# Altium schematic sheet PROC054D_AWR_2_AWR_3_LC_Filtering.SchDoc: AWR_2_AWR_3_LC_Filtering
size 558 x 431 mm; Date: Not shown in title block; ApprovedBy: Not shown in title block; CheckedBy: Not shown in title block; Author: Not shown in title block; CompanyName: Not shown in title block; DrawnBy: a0271760; Engineer: Not shown in title block; Organization: Not shown in title block; Address1: Not shown in title block; Address2: Not shown in title block; Address3: Not shown in title block; Address4: Not shown in title block; DocumentNumber: 7; Revision: Use project pAWRameter SCH_Rev; SheetNumber: 7; SheetTotal: 19; PageSetup: Record=PageOptions¦CenterHorizontal=True¦CenterVertical=True¦PrintScale=1.00¦XCorrection=1.00¦YCorrection=1.00¦PrintKind=0¦BorderSize=5000000¦LeftOffset=0¦BottomOffset=0¦Orientation=2¦PaperLength=1000¦PaperWidth=1000¦Scale=100¦PaperSource=15¦PrintQuality=600¦MediaType=1¦DitherType=10¦PaperKind=Letter¦PrintScaleMode=1
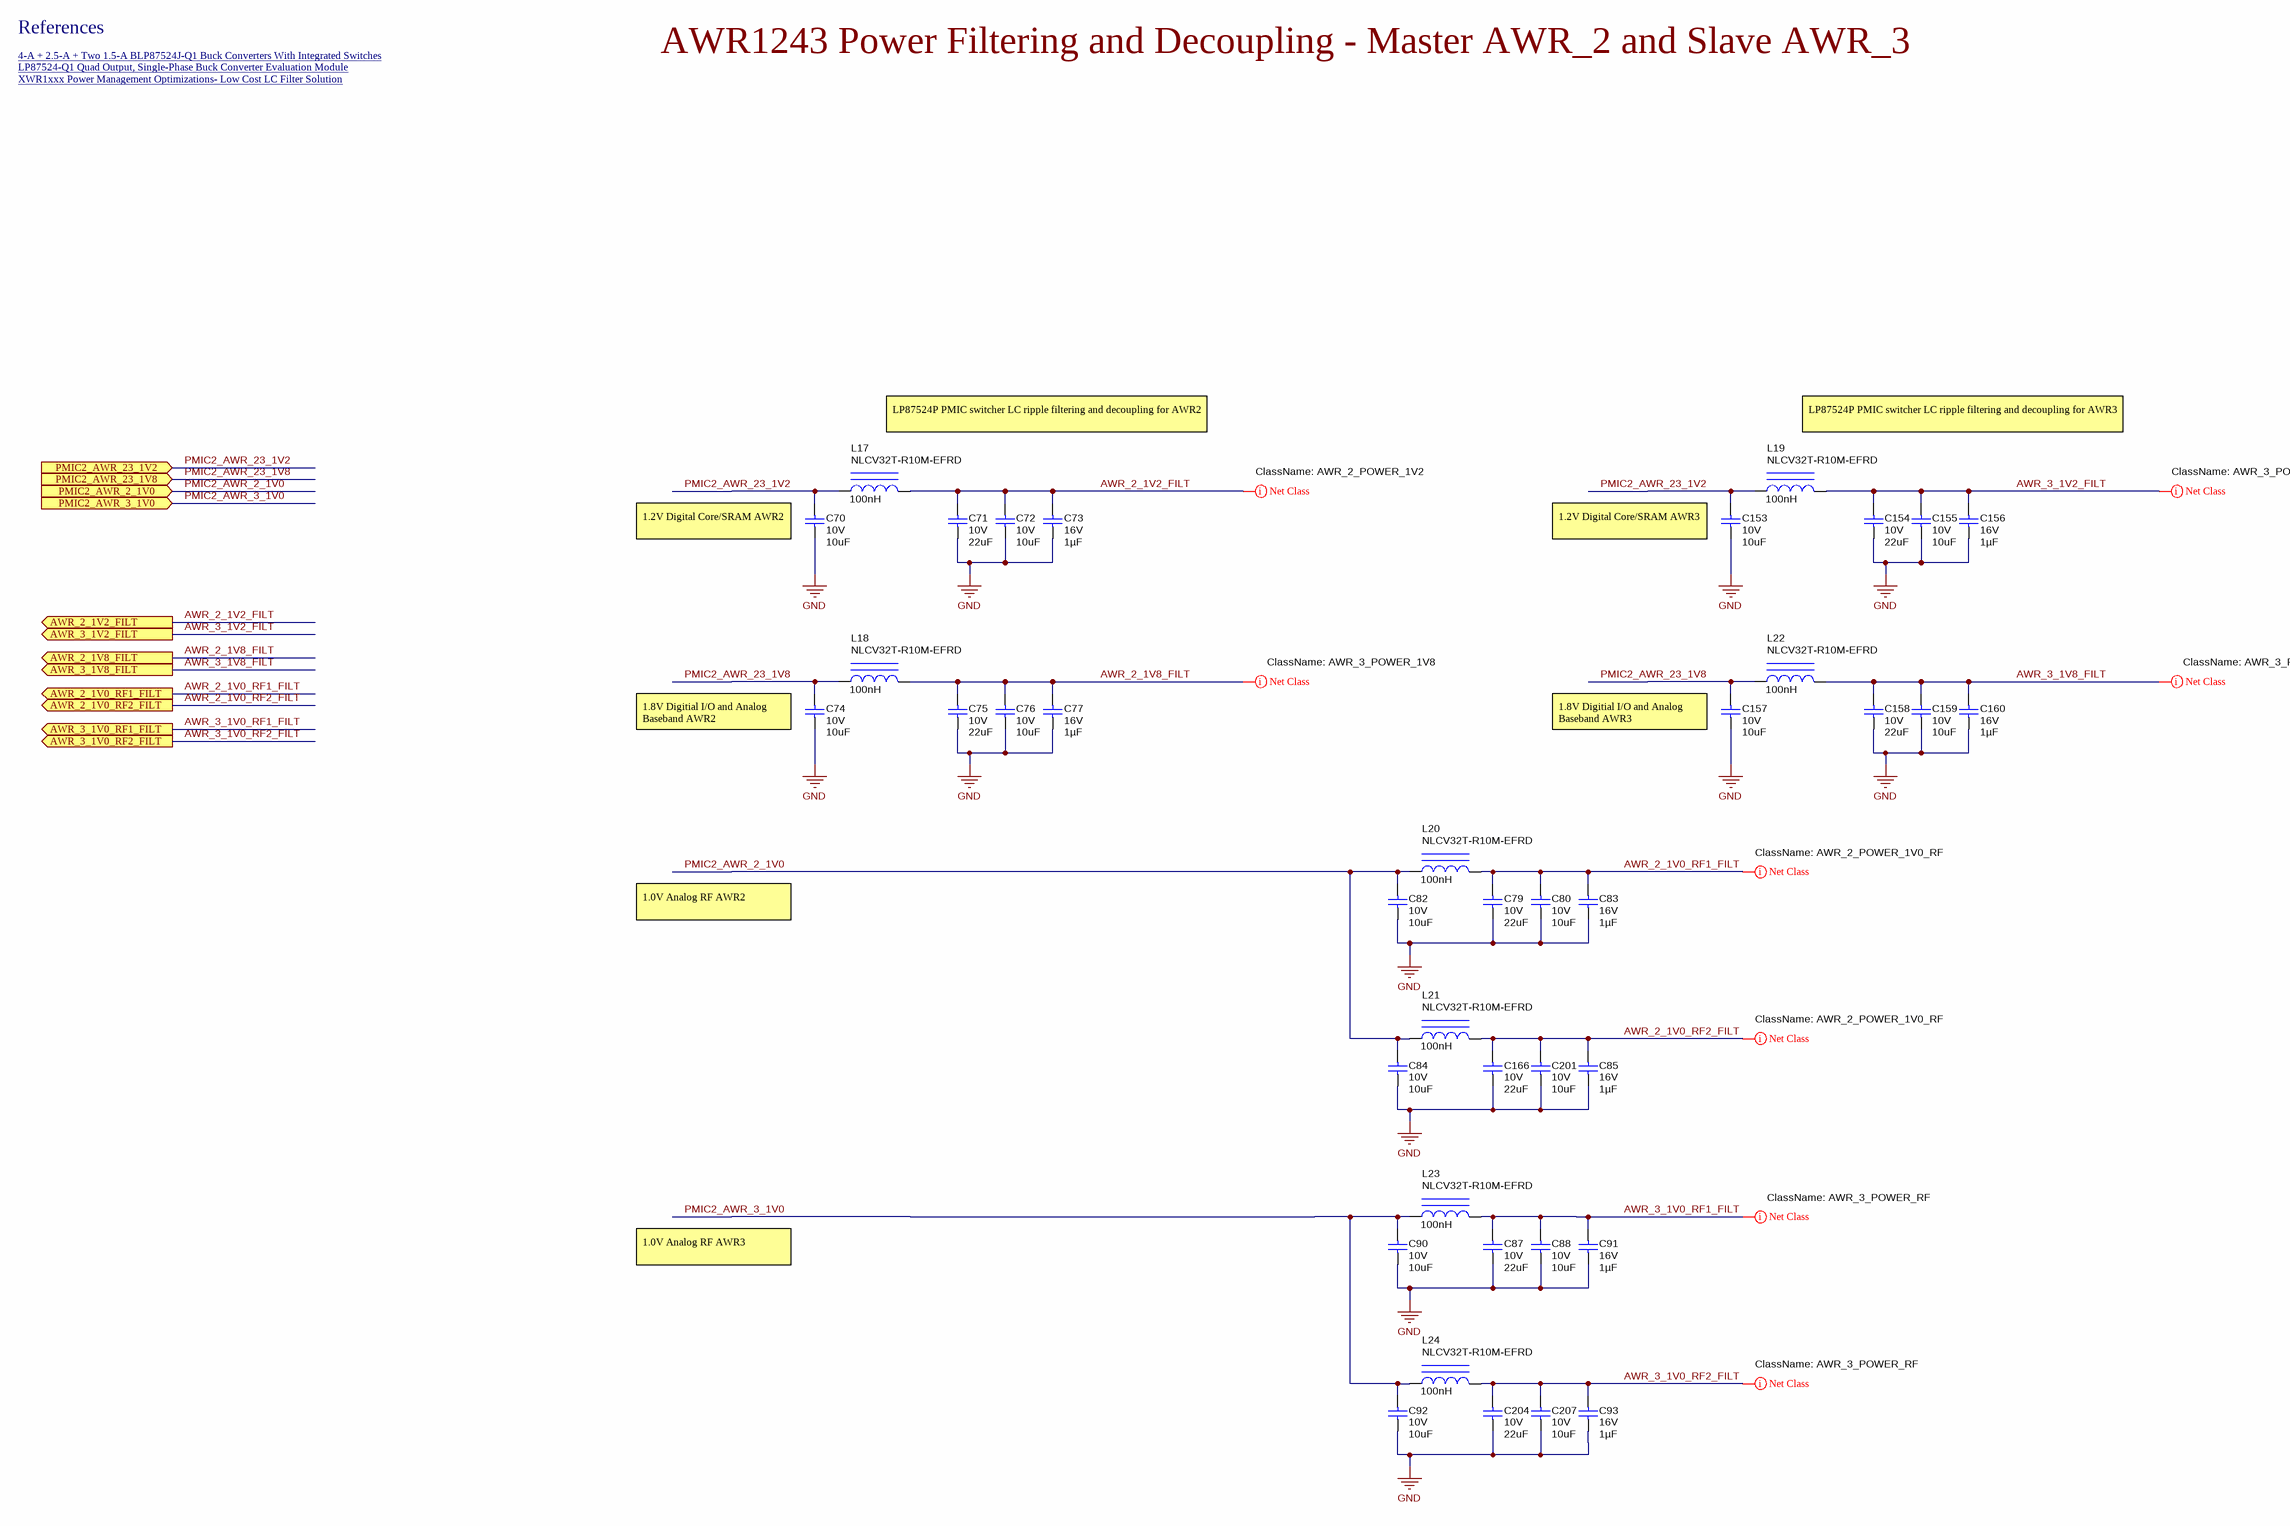
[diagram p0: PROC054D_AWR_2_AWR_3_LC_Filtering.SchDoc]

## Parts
C70  VDC_V: 10V  ValueDisplayed: 10uF  [0805L]  (hidden comment: GCM21BR71A106KE22L)
C71  VDC_V: 10V  ValueDisplayed: 22uF  [1206_180L]  (hidden comment: GCM31CR71A226KE02)
C72  VDC_V: 10V  ValueDisplayed: 10uF  [0805L]  (hidden comment: GCM21BR71A106KE22L)
C73  VDC_V: 16V  ValueDisplayed: 1µF  [0603S]  (hidden comment: GCM188R71C105KA64J)
C74  VDC_V: 10V  ValueDisplayed: 10uF  [0805L]  (hidden comment: GCM21BR71A106KE22L)
C75  VDC_V: 10V  ValueDisplayed: 22uF  [1206_180L]  (hidden comment: GCM31CR71A226KE02)
C76  VDC_V: 10V  ValueDisplayed: 10uF  [0805L]  (hidden comment: GCM21BR71A106KE22L)
C77  VDC_V: 16V  ValueDisplayed: 1µF  [0603S]  (hidden comment: GCM188R71C105KA64J)
C79  VDC_V: 10V  ValueDisplayed: 22uF  [1206_180L]  (hidden comment: GCM31CR71A226KE02)
C80  VDC_V: 10V  ValueDisplayed: 10uF  [0805L]  (hidden comment: GCM21BR71A106KE22L)
C82  VDC_V: 10V  ValueDisplayed: 10uF  [0805L]  (hidden comment: GCM21BR71A106KE22L)
C83  VDC_V: 16V  ValueDisplayed: 1µF  [0603S]  (hidden comment: GCM188R71C105KA64J)
C84  VDC_V: 10V  ValueDisplayed: 10uF  [0805L]  (hidden comment: GCM21BR71A106KE22L)
C85  VDC_V: 16V  ValueDisplayed: 1µF  [0603S]  (hidden comment: GCM188R71C105KA64J)
C87  VDC_V: 10V  ValueDisplayed: 22uF  [1206_180L]  (hidden comment: GCM31CR71A226KE02)
C88  VDC_V: 10V  ValueDisplayed: 10uF  [0805L]  (hidden comment: GCM21BR71A106KE22L)
C90  VDC_V: 10V  ValueDisplayed: 10uF  [0805L]  (hidden comment: GCM21BR71A106KE22L)
C91  VDC_V: 16V  ValueDisplayed: 1µF  [0603S]  (hidden comment: GCM188R71C105KA64J)
C92  VDC_V: 10V  ValueDisplayed: 10uF  [0805L]  (hidden comment: GCM21BR71A106KE22L)
C93  VDC_V: 16V  ValueDisplayed: 1µF  [0603S]  (hidden comment: GCM188R71C105KA64J)
C153  VDC_V: 10V  ValueDisplayed: 10uF  [0805L]  (hidden comment: GCM21BR71A106KE22L)
C154  VDC_V: 10V  ValueDisplayed: 22uF  [1206_180L]  (hidden comment: GCM31CR71A226KE02)
C155  VDC_V: 10V  ValueDisplayed: 10uF  [0805L]  (hidden comment: GCM21BR71A106KE22L)
C156  VDC_V: 16V  ValueDisplayed: 1µF  [0603S]  (hidden comment: GCM188R71C105KA64J)
C157  VDC_V: 10V  ValueDisplayed: 10uF  [0805L]  (hidden comment: GCM21BR71A106KE22L)
C158  VDC_V: 10V  ValueDisplayed: 22uF  [1206_180L]  (hidden comment: GCM31CR71A226KE02)
C159  VDC_V: 10V  ValueDisplayed: 10uF  [0805L]  (hidden comment: GCM21BR71A106KE22L)
C160  VDC_V: 16V  ValueDisplayed: 1µF  [0603S]  (hidden comment: GCM188R71C105KA64J)
C166  VDC_V: 10V  ValueDisplayed: 22uF  [1206_180L]  (hidden comment: GCM31CR71A226KE02)
C201  VDC_V: 10V  ValueDisplayed: 10uF  [0805L]  (hidden comment: GCM21BR71A106KE22L)
C204  VDC_V: 10V  ValueDisplayed: 22uF  [1206_180L]  (hidden comment: GCM31CR71A226KE02)
C207  VDC_V: 10V  ValueDisplayed: 10uF  [0805L]  (hidden comment: GCM21BR71A106KE22L)
L17  ValueDisplayed: 100nH  [NLCV32]  (hidden comment: NLCV32T-R10M-EFRD)
L18  ValueDisplayed: 100nH  [NLCV32]  (hidden comment: NLCV32T-R10M-EFRD)
L19  ValueDisplayed: 100nH  [NLCV32]  (hidden comment: NLCV32T-R10M-EFRD)
L20  ValueDisplayed: 100nH  [NLCV32]  (hidden comment: NLCV32T-R10M-EFRD)
L21  ValueDisplayed: 100nH  [NLCV32]  (hidden comment: NLCV32T-R10M-EFRD)
L22  ValueDisplayed: 100nH  [NLCV32]  (hidden comment: NLCV32T-R10M-EFRD)
L23  ValueDisplayed: 100nH  [NLCV32]  (hidden comment: NLCV32T-R10M-EFRD)
L24  ValueDisplayed: 100nH  [NLCV32]  (hidden comment: NLCV32T-R10M-EFRD)

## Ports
AWR_2_1V0_RF1_FILT (out), AWR_2_1V0_RF2_FILT (out), AWR_2_1V2_FILT (out), AWR_2_1V8_FILT (out), AWR_3_1V0_RF1_FILT (out), AWR_3_1V0_RF2_FILT (out), AWR_3_1V2_FILT (out), AWR_3_1V8_FILT (out), PMIC2_AWR_2_1V0 (in), PMIC2_AWR_3_1V0 (in), PMIC2_AWR_23_1V2 (in), PMIC2_AWR_23_1V8 (in)

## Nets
GND: C70.2 C71.2 C72.2 C73.2 C74.2 C75.2 C76.2 C77.2 C79.2 C80.2 C82.2 C83.2 C84.2 C85.2 C87.2 C88.2 C90.2 C91.2 C92.2 C93.2 C153.2 C154.2 C155.2 C156.2 C157.2 C158.2 C159.2 C160.2 C166.2 C201.2 C204.2 C207.2
AWR_2_1V0_RF1_FILT: C79.1 C80.1 C83.1 L20.2 ; port AWR_2_1V0_RF1_FILT
AWR_2_1V0_RF2_FILT: C85.1 C166.1 C201.1 L21.2 ; port AWR_2_1V0_RF2_FILT
AWR_2_1V2_FILT: C71.1 C72.1 C73.1 L17.2 ; port AWR_2_1V2_FILT
AWR_2_1V8_FILT: C75.1 C76.1 C77.1 L18.2 ; port AWR_2_1V8_FILT
AWR_3_1V0_RF1_FILT: C87.1 C88.1 C91.1 L23.2 ; port AWR_3_1V0_RF1_FILT
AWR_3_1V0_RF2_FILT: C93.1 C204.1 C207.1 L24.2 ; port AWR_3_1V0_RF2_FILT
AWR_3_1V2_FILT: C154.1 C155.1 C156.1 L19.2 ; port AWR_3_1V2_FILT
AWR_3_1V8_FILT: C158.1 C159.1 C160.1 L22.2 ; port AWR_3_1V8_FILT
PMIC2_AWR_2_1V0: C82.1 C84.1 L20.1 L21.1 ; port PMIC2_AWR_2_1V0
PMIC2_AWR_3_1V0: C90.1 C92.1 L23.1 L24.1 ; port PMIC2_AWR_3_1V0
PMIC2_AWR_23_1V2: C70.1 C153.1 L17.1 L19.1 ; port PMIC2_AWR_23_1V2
PMIC2_AWR_23_1V8: C74.1 C157.1 L18.1 L22.1 ; port PMIC2_AWR_23_1V8

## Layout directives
net class AWR_2_POWER_1V2: AWR_2_1V2_FILT
net class AWR_2_POWER_1V0_RF: AWR_2_1V0_RF1_FILT, AWR_2_1V0_RF2_FILT
net class AWR_3_POWER_RF: AWR_3_1V0_RF1_FILT, AWR_3_1V0_RF2_FILT
net class AWR_3_POWER_1V8: AWR_2_1V8_FILT, AWR_3_1V8_FILT
net class AWR_3_POWER_1V2: AWR_3_1V2_FILT

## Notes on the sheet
- References
- 4-A + 2.5-A + Two 1.5-A BLP87524J-Q1 Buck Converters With Integrated Switches <http://www.ti.com/product/lp87524j-q1>
- LP87524-Q1 Quad Output, Single-Phase Buck Converter Evaluation Module <http://www.ti.com/tool/lp87524q1evm>
- XWR1xxx Power Management Optimizations- Low Cost LC Filter Solution <http://www.ti.com/lit/pdf/swra577>
- AWR1243 Power Filtering and Decoupling - Master AWR_2 and Slave AWR_3
- LP87524P PMIC switcher LC ripple filtering and decoupling for AWR2
- LP87524P PMIC switcher LC ripple filtering and decoupling for AWR3
- (near C70) 1.2V Digital Core/SRAM AWR2
- (near C153) 1.2V Digital Core/SRAM AWR3
- (near C74) 1.8V Digitial I/O and Analog Baseband AWR2
- (near C157) 1.8V Digitial I/O and Analog Baseband AWR3
- 1.0V Analog RF AWR2
- 1.0V Analog RF AWR3

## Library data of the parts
C70 C72 C74 C76 C80 C82 C84 C88 C90 C92 C153 C155 C157 C159 C201 C207 = CMP-0008017-2: CAP, CERM, 10 uF, 10 V, +/- 10%, X7R, 0805; Manufacturer: MuRata; TaMin_C: -55°C; Polarized: N; SizeAreaWB_mm2: 6.75; Value1: Unknown; U/M: EA; Value: 10uF; TaMax_C: 125°C; SizeZ_mm: 1.45; SizeX_mm: 2; SizeY_mm: 1.25; Cap_Case: 0805; SizeArea_mm2: 2.5; Cap_F: 10µF; AEC Category: Q200
C71 C75 C79 C87 C154 C158 C166 C204 = CMP-0008811-2: CAP, CERM, 22 uF, 10 V, +/- 10%, X7R, AEC-Q200 Grade 1, 1206; Manufacturer: MuRata; TaMin_C: -55°C; Polarized: N; SizeAreaWB_mm2: 10.92; Value1: Unknown; U/M: EA; Value: 22uF; TaMax_C: 125°C; SizeZ_mm: 1.8; SizeX_mm: 3.2; SizeY_mm: 1.6; Cap_Case: 1206; SizeArea_mm2: 5.12; AEC Qualified: Y; Cap_F: 22µF; AEC Grade: 1; AEC Category: Q200
C73 C77 C83 C85 C91 C93 C156 C160 = CMP-0079154-1: CAP, CERM, 1 µF, 16 V,+/- 10%, X7R, AEC-Q200 Grade 1, 0603; Manufacturer: MuRata; SizeAreaWB_mm2: 4.68; SizeArea_mm2: 1.28; AEC Qualified: Y; AEC Category: Q200; Value: 1uF; TaMax_C: 125°C; SizeZ_mm: 1; Polarized: N; TaMin_C: -55°C; SizeY_mm: 0.8; U/M: EA; SizeX_mm: 1.6; Cap_Case: 0603
L17-L24 = CMP-0083745-1: Inductor, Wirewound, Ferrite, 100 nH, 2.85 A, 0.024 ohm, AEC-Q200 Grade 1, SMD; Manufacturer: TDK; Isat: 2.85A @ 10% inductance drop; Irms: 2.85A @ 40C rise; SizeAreaWB_mm2: 13.44; DCR_ohm: 0.024; Value: 100nH; Imax_A: 2.85A; SizeZ_mm: 2.5; SizeX_mm: 3.2; SizeY_mm: 2.2; SizeArea_mm2: 7.04; AEC Qualified: Y; AEC Grade: 1; AEC Category: Q200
